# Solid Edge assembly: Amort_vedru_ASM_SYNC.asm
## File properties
Author: KULL
Template: Iso Metric Assembly.asm
Last saved by: KULL
Revision: 4
Application: Solid Edge
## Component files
Amort_sync.par
vedru__sync.par
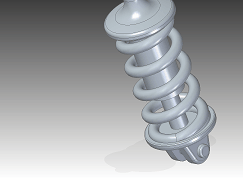
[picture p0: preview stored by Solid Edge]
